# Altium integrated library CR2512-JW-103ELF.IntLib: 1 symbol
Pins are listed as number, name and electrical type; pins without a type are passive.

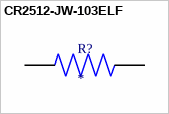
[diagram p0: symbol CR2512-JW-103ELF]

## CR2512-JW-103ELF
designator R?
10 kOhms Â±5% 1W Chip Resistor 2512 (6432 Metric) Thick Film; MP: CR2512-JW-103ELF; MF: Bourns
footprint RESC6331X75N
pins: 1, 2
